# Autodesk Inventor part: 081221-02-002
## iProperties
Created: 2008-12
Part Number: 081221-02-002
Document SubType Name: Modeling
Designer: Steve
Density: 1 g/cm^3
Author: Steve
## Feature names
1. Extrusion1
2. Extrusion2
3. Extrusion3
4. Extrusion4
5. Extrusion5
6. Extrusion6
7. Fillet1
8. Hole1
9. Hole2
10. Rechteckige Anordnung1 [Rectangular Pattern]
